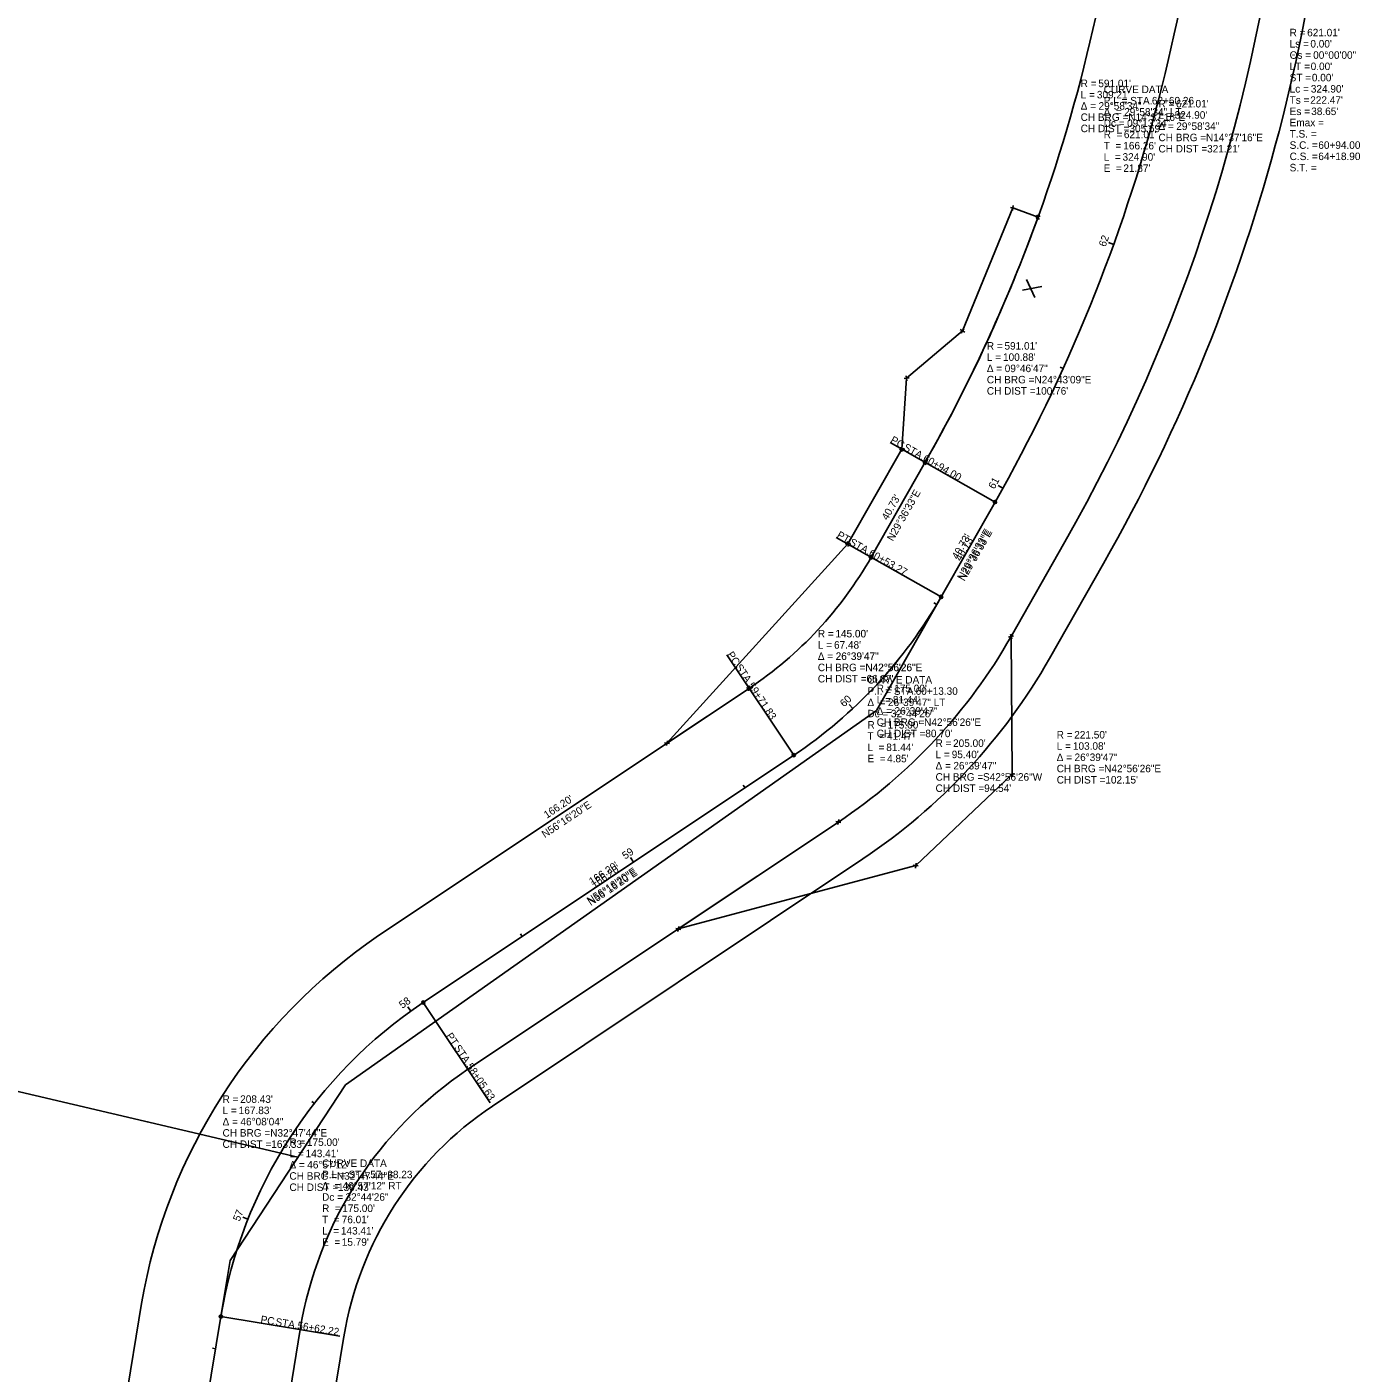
# Model space of a CAD drawing. Extents: x 2346746 to 2349554, y 247132 to 249252.
# Drawn here: x 2347228 to 2347725, y 247688 to 248191 of the extents above; entities that cross this region are included whole.
import ezdxf

# ---------------------------------------------------------------- set-up
doc = ezdxf.new("R2010")
doc.units = 0
for name, color, linetype in [('_CIVIL_CONSTRUCTION', 7, 'Continuous'), ('Default', 7, 'Continuous'), ('PF_X_Ground_Line', 7, 'Continuous'), ('UT_X_FO', 7, 'Continuous'), ('UT_X_Telecom', 7, 'Continuous'), ('V-SURV-ANNO', 7, 'Continuous'), ('V-SURV-IPF', 7, 'Continuous'), ('V-TOPO-ANNO', 7, 'Continuous'), ('V-TOPO-BNDY', 7, 'Continuous'), ('V-TOPO-FEAT', 7, 'Continuous'), ('V-TOPO-USER', 7, 'Continuous'), ('V-TOPO-WSHD', 7, 'Continuous'), ('V-UTIL-NGAS-STRC', 7, 'Continuous'), ('V-UTIL-STRM-STRC', 7, 'Continuous'), ('V-UTIL-WATR-LINE-ANNO', 7, 'Continuous'), ('V-UTIL-WATR-STRC', 7, 'Continuous')]:
    doc.layers.add(name, color=color, linetype=linetype)

msp = doc.modelspace()

# ---------------------------------------------------------------- linework, layer by layer
at = {"layer": '_CIVIL_CONSTRUCTION'}
for p, q in [((2347589.25, 248013.29), (2347550.12, 248035.52)), ((2347569.12, 247977.88), (2347530, 248000.11)), ((2347514.14, 247918.8), (2347489.16, 247956.22)), ((2347375.92, 247826.51), (2347400.9, 247789.09)), ((2347300.4, 247709.31), (2347344.8, 247702.02))]:
    msp.add_line(p, q, dxfattribs=at)
for centre in [(2347589.25, 248013.29), (2347569.12, 247977.88), (2347514.14, 247918.8), (2347375.92, 247826.51), (2347300.4, 247709.31)]:
    msp.add_circle(centre, 0.6, dxfattribs=at)
at = {"layer": 'Default'}
for p, q in [((2347548.13, 247948.47), (2347553.24, 247954.53)), ((2347548.13, 247948.47), (2347552.7, 247953.87)), ((2347525.99, 247947.23), (2347525.99, 247947.23))]:
    msp.add_line(p, q, dxfattribs=at)
at = {"layer": 'UT_X_FO'}
for p, q in [((2347569.12, 247977.88), (2347589.25, 248013.29)), ((2347375.92, 247826.51), (2347514.14, 247918.8)), ((2347286.36, 247623.78), (2347300.4, 247709.31))]:
    msp.add_line(p, q, dxfattribs=at)
for centre, radius, start, end in [((2347049.33, 248320.12), 621.01, 330.3908, 0.36691), ((2347416.98, 248064.34), 175, 303.7279, 330.3908), ((2347473.09, 247680.97), 175, 123.7279, 170.6811)]:
    msp.add_arc(centre, radius, start, end, dxfattribs=at)
at = {"layer": 'V-SURV-ANNO'}
for p, q in [((2347648.57, 248157.12), (2347647.41, 248157.44)), ((2347633.52, 248109.46), (2347631.64, 248110.14)), ((2347614.69, 248063.16), (2347613.59, 248063.65)), ((2347592.19, 248018.52), (2347590.44, 248019.49)), ((2347567.48, 247975.05), (2347566.45, 247975.66)), ((2347536.21, 247936.25), (2347534.85, 247937.71)), ((2347495.99, 247906.67), (2347495.32, 247907.67)), ((2347454.4, 247878.91), (2347453.29, 247880.57)), ((2347412.82, 247851.15), (2347412.15, 247852.15)), ((2347371.29, 247823.31), (2347370.12, 247824.94)), ((2347335.29, 247788.85), (2347334.35, 247789.59)), ((2347310.47, 247745.64), (2347308.62, 247746.38)), ((2347298.42, 247697.25), (2347297.23, 247697.44))]:
    msp.add_line(p, q, dxfattribs=at)
at = {"layer": 'V-TOPO-ANNO'}
for p, q in [((2347545, 247935.42), (2347569.12, 247977.88)), ((2347545, 247935.42), (2347569.12, 247977.88)), ((2347346.85, 247795.81), (2347545, 247935.42)), ((2347346.85, 247795.81), (2347545, 247935.42)), ((2347329.07, 247768.72), (2346848.6, 247881.75)), ((2347329.07, 247768.72), (2346848.6, 247881.75)), ((2347303.83, 247730.26), (2347346.85, 247795.81)), ((2347303.83, 247730.26), (2347346.85, 247795.81)), ((2347300.4, 247709.31), (2347303.83, 247730.26)), ((2347300.4, 247709.31), (2347303.83, 247730.26))]:
    msp.add_line(p, q, dxfattribs=at)
at = {"layer": 'V-TOPO-BNDY'}
for p, q in [((2347543.04, 247992.7), (2347563.17, 248028.11)), ((2347595.21, 247963.05), (2347615.33, 247998.46)), ((2347595.21, 247963.05), (2347615.33, 247998.46)), ((2347359.26, 247851.46), (2347497.49, 247943.75)), ((2347392.58, 247801.56), (2347530.8, 247893.85)), ((2347392.58, 247801.56), (2347530.8, 247893.85)), ((2347256.25, 247625.54), (2347270.79, 247714.16)), ((2347316.48, 247622.03), (2347330, 247704.45)), ((2347316.48, 247622.03), (2347330, 247704.45))]:
    msp.add_line(p, q, dxfattribs=at)
for centre, radius, start, end in [((2347049.33, 248320.12), 591.01, 330.3908, 0.36691), ((2347049.33, 248320.12), 651.01, 330.3908, 354.01806), ((2347049.33, 248320.12), 651.01, 330.3908, 354.01806), ((2347416.98, 248064.34), 145, 303.7279, 330.3908), ((2347416.98, 248064.34), 205, 303.7279, 330.3908), ((2347416.98, 248064.34), 205, 303.7279, 330.3908), ((2347476.23, 247678.94), 208.43, 124.1372, 170.2718), ((2347472.74, 247681.19), 144.62, 123.6631, 170.7459), ((2347472.74, 247681.19), 144.62, 123.6631, 170.7459)]:
    msp.add_arc(centre, radius, start, end, dxfattribs=at)
at = {"layer": 'V-TOPO-FEAT'}
for p, q in [((2347609.55, 247954.9), (2347629.68, 247990.31)), ((2347609.55, 247954.9), (2347629.68, 247990.31)), ((2347401.74, 247787.84), (2347539.96, 247880.12)), ((2347401.74, 247787.84), (2347539.96, 247880.12)), ((2347333.04, 247621.07), (2347346.28, 247701.78)), ((2347333.04, 247621.07), (2347346.28, 247701.78))]:
    msp.add_line(p, q, dxfattribs=at)
for centre, radius, start, end in [((2347049.33, 248320.12), 667.51, 330.3908, 0.36691), ((2347049.33, 248320.12), 667.51, 330.3908, 0.36691), ((2347416.98, 248064.34), 221.5, 303.7279, 330.3908), ((2347416.98, 248064.34), 221.5, 303.7279, 330.3908), ((2347473.09, 247680.97), 128.5, 123.7279, 170.6811), ((2347473.09, 247680.97), 128.5, 123.7279, 170.6811)]:
    msp.add_arc(centre, radius, start, end, dxfattribs=at)
at = {"layer": 'V-TOPO-USER'}
for p, q in [((2347594.96, 248123.18), (2347596.82, 248122.87)), ((2347595.74, 248122.1), (2347596.05, 248123.96)), ((2347604.46, 248119.21), (2347606.14, 248120.06)), ((2347605.73, 248118.79), (2347604.87, 248120.48)), ((2347576.28, 248077.62), (2347577.92, 248076.69)), ((2347576.64, 248076.33), (2347577.57, 248077.97)), ((2347556.15, 248060.41), (2347556.37, 248058.54)), ((2347555.32, 248059.37), (2347557.2, 248059.58)), ((2347553.57, 248032.78), (2347555.38, 248033.32)), ((2347554.74, 248032.15), (2347554.2, 248033.95)), ((2347562.26, 248027.84), (2347564.07, 248028.38)), ((2347563.44, 248027.21), (2347562.89, 248029.01)), ((2347533.44, 247997.39), (2347535.26, 247997.89)), ((2347534.6, 247996.73), (2347534.1, 247998.55)), ((2347542.13, 247992.44), (2347543.95, 247992.95)), ((2347543.3, 247991.79), (2347542.79, 247993.61)), ((2347594.3, 247962.8), (2347596.12, 247963.3)), ((2347595.46, 247962.14), (2347594.96, 247963.96)), ((2347496.56, 247943.92), (2347498.42, 247943.58)), ((2347497.32, 247942.82), (2347497.66, 247944.67)), ((2347465.93, 247923.47), (2347467.78, 247923.12)), ((2347466.68, 247922.37), (2347467.03, 247924.22)), ((2347594.73, 247911.64), (2347596.61, 247911.79)), ((2347595.74, 247910.77), (2347595.59, 247912.65)), ((2347530.61, 247892.92), (2347530.99, 247894.77)), ((2347529.88, 247894.03), (2347531.73, 247893.66)), ((2347558.72, 247877.75), (2347560.59, 247877.47)), ((2347559.52, 247876.68), (2347559.8, 247878.55)), ((2347470.87, 247853.04), (2347471.25, 247854.88)), ((2347470.14, 247854.15), (2347471.98, 247853.77))]:
    msp.add_line(p, q, dxfattribs=at)
at = {"layer": 'V-TOPO-WSHD'}
for p, q in [((2347577.1, 248077.15), (2347595.89, 248123.03)), ((2347595.89, 248123.03), (2347605.3, 248119.63)), ((2347556.26, 248059.47), (2347577.1, 248077.15)), ((2347554.47, 248033.05), (2347556.26, 248059.47)), ((2347534.35, 247997.64), (2347554.47, 248033.05)), ((2347466.85, 247923.29), (2347534.35, 247997.64)), ((2347595.67, 247911.71), (2347595.21, 247963.05)), ((2347559.66, 247877.61), (2347595.67, 247911.71)), ((2347471.06, 247853.96), (2347559.66, 247877.61))]:
    msp.add_line(p, q, dxfattribs=at)
at = {"layer": 'V-UTIL-NGAS-STRC'}
for p, q in [((2347577.1, 248077.15), (2347595.89, 248123.03)), ((2347595.89, 248123.03), (2347605.3, 248119.63)), ((2347556.26, 248059.47), (2347577.1, 248077.15)), ((2347554.47, 248033.05), (2347556.26, 248059.47)), ((2347534.35, 247997.64), (2347554.47, 248033.05)), ((2347563.17, 248028.11), (2347543.04, 247992.7)), ((2347466.85, 247923.29), (2347534.35, 247997.64)), ((2347595.21, 247963.05), (2347595.67, 247911.71)), ((2347497.49, 247943.75), (2347466.85, 247923.29)), ((2347595.67, 247911.71), (2347559.66, 247877.61)), ((2347471.06, 247853.96), (2347530.8, 247893.85)), ((2347559.66, 247877.61), (2347471.06, 247853.96))]:
    msp.add_line(p, q, dxfattribs=at)
for centre, radius, start, end in [((2347049.33, 248320.12), 591.01, 330.3908, 340.17061), ((2347416.98, 248064.34), 145, 303.7279, 330.3908), ((2347416.98, 248064.34), 205, 303.7279, 330.3908)]:
    msp.add_arc(centre, radius, start, end, dxfattribs=at)
at = {"layer": 'V-UTIL-STRM-STRC'}
for p, q in [((2347601.01, 248096.38), (2347604.08, 248089.65)), ((2347599.45, 248092.33), (2347606.66, 248093.78))]:
    msp.add_line(p, q, dxfattribs=at)

# ---------------------------------------------------------------- texts
at = {"layer": '_CIVIL_CONSTRUCTION'}
for s, rotation, p in [('PC', 330.3908, (2347549.95, 248035.66)), (' STA. ', 330.3908, (2347553.95, 248033.39)), ('60+94.00', 330.3908, (2347562.06, 248028.78)), ('PT', 330.3908, (2347529.96, 248000.18)), (' STA. ', 330.3908, (2347533.74, 247998.03)), ('60+53.27', 330.3908, (2347541.85, 247993.42)), ('PC', 303.7279, (2347489.11, 247956.37)), (' STA. ', 303.7279, (2347491.66, 247952.54)), ('59+71.83', 303.7279, (2347496.84, 247944.79)), ('PT', 303.7279, (2347384.26, 247814.08)), (' STA. ', 303.7279, (2347386.68, 247810.46)), ('58+05.63', 303.7279, (2347391.86, 247802.71)), ('PC', 350.6811, (2347315.04, 247706.94)), (' STA. ', 350.6811, (2347319.58, 247706.19)), ('56+62.22', 350.6811, (2347328.78, 247704.68))]:
    msp.add_text(s, height=2.8, rotation=rotation, dxfattribs=at).set_placement(p)
at = {"layer": 'Default'}
for s, p in [('R = ', (2347621.2, 248168.13)), ("591.01'", (2347627.79, 248168.13)), ('L = ', (2347621.2, 248163.93)), ("309.21'", (2347627.25, 248163.93)), ('Δ = ', (2347621.2, 248159.73)), ('29°58\'34"', (2347627.88, 248159.73)), ('CH BRG = ', (2347621.2, 248155.53)), ('N14°37\'16"E', (2347638.98, 248155.53)), ('CH DIST = ', (2347621.2, 248151.33)), ("305.69'", (2347639.39, 248151.33)), ('R = ', (2347586.19, 248070.17)), ("591.01'", (2347592.77, 248070.17)), ('L = ', (2347586.19, 248065.97)), ("100.88'", (2347592.23, 248065.97)), ('Δ = ', (2347586.19, 248061.77)), ('CH BRG = ', (2347586.19, 248057.57)), ('09°46\'47"', (2347592.87, 248061.77)), ('N24°43\'09"E', (2347603.97, 248057.57)), ('CH DIST = ', (2347586.19, 248053.37)), ("100.76'", (2347604.37, 248053.37)), ('R = ', (2347523.13, 247962.76)), ("145.00'", (2347529.71, 247962.76)), ('L = ', (2347523.13, 247958.56)), ("67.48'", (2347529.17, 247958.56)), ('Δ = ', (2347523.13, 247954.36)), ('26°39\'47"', (2347529.81, 247954.36)), ('CH BRG = ', (2347523.13, 247950.16)), ('N42°56\'26"E', (2347540.91, 247950.16)), ('CH DIST = ', (2347523.13, 247945.96)), ("66.87'", (2347541.31, 247945.96)), ('R = ', (2347301.02, 247789.04)), ("208.43'", (2347307.6, 247789.04)), ('L = ', (2347301.02, 247784.84)), ("167.83'", (2347307.06, 247784.84)), ('Δ = ', (2347301.02, 247780.64)), ('CH BRG = ', (2347301.02, 247776.44)), ('46°08\'04"', (2347307.7, 247780.64)), ('N32°47\'44"E', (2347318.8, 247776.44)), ('CH DIST = ', (2347301.02, 247772.24)), ("163.33'", (2347319.2, 247772.24))]:
    msp.add_text(s, height=2.8, dxfattribs=at).set_placement(p)
at = {"layer": 'PF_X_Ground_Line'}
for s, rotation, p in [('N29°36\'33"E', 60.3908, (2347577.87, 247983.54)), ('N56°16\'20"E', 33.7279, (2347438.45, 247862.49))]:
    msp.add_text(s, height=2.8, rotation=rotation, dxfattribs=at).set_placement(p)
at = {"layer": 'UT_X_Telecom'}
for s, p in [('R = ', (2347699.17, 248187.11)), ("621.01'", (2347705.71, 248187.11)), ('Θs = ', (2347699.17, 248178.71)), ('Ls = ', (2347699.17, 248182.91)), ("0.00'", (2347706.91, 248182.91)), ('00°00\'00"', (2347707.95, 248178.71)), ('LT = ', (2347699.17, 248174.51)), ("0.00'", (2347707.02, 248174.51)), ('ST = ', (2347699.17, 248170.31)), ("0.00'", (2347707.47, 248170.31)), ('CURVE DATA', (2347629.79, 248165.89)), ('Lc = ', (2347699.17, 248166.11)), ("324.90'", (2347707.08, 248166.11)), ('P.I. = STA. ', (2347629.79, 248161.69)), ('62+60.26', (2347647.78, 248161.69)), ('Ts = ', (2347699.17, 248161.91)), ("222.47'", (2347706.85, 248161.91)), ('Δ  = ', (2347629.79, 248157.49)), ('Dc = ', (2347629.79, 248153.29)), ('29°58\'34" LT', (2347637.43, 248157.49)), ('09°13\'34"', (2347638.53, 248153.29)), ('Es = ', (2347699.17, 248157.71)), ('Emax = ', (2347699.17, 248153.51)), ("38.65'", (2347707.22, 248157.71)), ('R  = ', (2347629.79, 248149.09)), ("621.01'", (2347637.32, 248149.09)), ('T.S. = ', (2347699.17, 248149.31)), ('T  = ', (2347629.79, 248144.89)), ("166.26'", (2347637.11, 248144.89)), ('S.C. = ', (2347699.17, 248145.11)), ('60+94.00', (2347709.87, 248145.11)), ('L  = ', (2347629.79, 248140.69)), ("324.90'", (2347636.82, 248140.69)), ('C.S. = ', (2347699.17, 248140.91)), ('64+18.90', (2347709.87, 248140.91)), ('E  = ', (2347629.79, 248136.49)), ("21.87'", (2347637.13, 248136.49)), ('S.T. = ', (2347699.17, 248136.71)), ('CURVE DATA', (2347541.63, 247945.54)), ('Δ  = ', (2347541.63, 247937.14)), ('P.I. = STA. ', (2347541.63, 247941.34)), ('26°39\'47" LT', (2347549.28, 247937.14)), ('60+13.30', (2347559.63, 247941.34)), ('Dc = ', (2347541.63, 247932.94)), ('32°44\'26"', (2347550.38, 247932.94)), ('R  = ', (2347541.63, 247928.74)), ("175.00'", (2347549.17, 247928.74)), ('T  = ', (2347541.63, 247924.54)), ("41.47'", (2347548.95, 247924.54)), ('L  = ', (2347541.63, 247920.34)), ("81.44'", (2347548.67, 247920.34)), ('E  = ', (2347541.63, 247916.14)), ("4.85'", (2347548.98, 247916.14)), ('CURVE DATA', (2347338.16, 247765.11)), ('Δ  = ', (2347338.16, 247756.71)), ('P.I. = STA. ', (2347338.16, 247760.91)), ('46°57\'12" RT', (2347345.8, 247756.71)), ('57+38.23', (2347356.15, 247760.91)), ('Dc = ', (2347338.16, 247752.51)), ('32°44\'26"', (2347346.9, 247752.51)), ('R  = ', (2347338.16, 247748.31)), ("175.00'", (2347345.69, 247748.31)), ('T  = ', (2347338.16, 247744.11)), ("76.01'", (2347345.48, 247744.11)), ('L  = ', (2347338.16, 247739.91)), ("143.41'", (2347345.19, 247739.91)), ('E  = ', (2347338.16, 247735.71)), ("15.79'", (2347345.5, 247735.71))]:
    msp.add_text(s, height=2.8, dxfattribs=at).set_placement(p)
at = {"layer": 'V-SURV-ANNO'}
for s, rotation, p in [('62', 70.1706, (2347630.46, 248108.34)), ('61', 60.9444, (2347588.98, 248017.89)), ('60', 42.9499, (2347532.94, 247936.61)), ('59', 33.7279, (2347451.26, 247879.82)), ('58', 35.5715, (2347368.1, 247824.1)), ('57', 68.312, (2347307.37, 247744.59))]:
    msp.add_text(s, height=2.8, rotation=rotation, dxfattribs=at).set_placement(p)
at = {"layer": 'V-SURV-IPF'}
for s, rotation, p in [("40.73'", 60.3908, (2347576.53, 247990.97)), ("166.20'", 33.7279, (2347439.66, 247869.11))]:
    msp.add_text(s, height=2.8, rotation=rotation, dxfattribs=at).set_placement(p)
at = {"layer": 'V-UTIL-WATR-LINE-ANNO'}
for s, p in [('R = ', (2347650.23, 248160.56)), ("621.01'", (2347656.77, 248160.56)), ('L = ', (2347650.23, 248156.36)), ("324.90'", (2347656.27, 248156.36)), ('Δ = ', (2347650.23, 248152.16)), ('CH BRG = ', (2347650.23, 248147.96)), ('29°58\'34"', (2347656.88, 248152.16)), ('N14°37\'16"E', (2347667.95, 248147.96)), ('CH DIST = ', (2347650.23, 248143.76)), ("321.21'", (2347668.37, 248143.76)), ('R = ', (2347523.13, 247962.76)), ("145.00'", (2347529.66, 247962.76)), ('L = ', (2347523.13, 247958.56)), ("67.48'", (2347529.16, 247958.56)), ('Δ = ', (2347523.13, 247954.36)), ('26°39\'47"', (2347529.77, 247954.36)), ('CH BRG = ', (2347523.13, 247950.16)), ('N42°56\'26"E', (2347540.84, 247950.16)), ('CH DIST = ', (2347523.13, 247945.96)), ("66.87'", (2347541.27, 247945.96)), ('R = ', (2347545.09, 247942.32)), ("175.00'", (2347551.63, 247942.32)), ('L = ', (2347545.09, 247938.12)), ("81.44'", (2347551.13, 247938.12)), ('Δ = ', (2347545.09, 247933.92)), ('26°39\'47"', (2347551.74, 247933.92)), ('CH BRG = ', (2347545.09, 247929.72)), ('N42°56\'26"E', (2347562.8, 247929.72)), ('CH DIST = ', (2347545.09, 247925.52)), ("80.70'", (2347563.23, 247925.52)), ('R = ', (2347567.05, 247921.89)), ("205.00'", (2347573.59, 247921.89)), ('R = ', (2347612.26, 247925.03)), ("221.50'", (2347618.8, 247925.03)), ('L = ', (2347567.05, 247917.69)), ("95.40'", (2347573.09, 247917.69)), ('L = ', (2347612.26, 247920.83)), ("103.08'", (2347618.3, 247920.83)), ('Δ = ', (2347567.05, 247913.49)), ('26°39\'47"', (2347573.7, 247913.49)), ('Δ = ', (2347612.26, 247916.63)), ('CH BRG = ', (2347612.26, 247912.43)), ('26°39\'47"', (2347618.91, 247916.63)), ('N42°56\'26"E', (2347629.97, 247912.43)), ('CH BRG = ', (2347567.05, 247909.29)), ('S42°56\'26"W', (2347584.76, 247909.29)), ('CH DIST = ', (2347612.26, 247908.23)), ("102.15'", (2347630.4, 247908.23)), ('CH DIST = ', (2347567.05, 247905.09)), ("94.54'", (2347585.19, 247905.09)), ('R = ', (2347325.98, 247772.96)), ("175.00'", (2347332.52, 247772.96)), ('L = ', (2347325.98, 247768.76)), ("143.41'", (2347332.02, 247768.76)), ('Δ = ', (2347325.98, 247764.56)), ('46°57\'12"', (2347332.63, 247764.56)), ('CH BRG = ', (2347325.98, 247760.36)), ('CH DIST = ', (2347325.98, 247756.16)), ('N32°47\'44"E', (2347343.69, 247760.36)), ("139.43'", (2347344.12, 247756.16))]:
    msp.add_text(s, height=2.8, dxfattribs=at).set_placement(p)
for s, rotation, p in [("40.73'", 60.3908, (2347575.34, 247991.65)), ('N29°36\'33"E', 60.3908, (2347577.34, 247983.84)), ('N56°16\'20"E', 33.7279, (2347438.12, 247862.99)), ("166.20'", 33.7279, (2347438.9, 247870.24))]:
    msp.add_text(s, height=2.8, rotation=rotation, dxfattribs=at).set_placement(p)
at = {"layer": 'V-UTIL-WATR-STRC'}
for s, rotation, p in [("40.73'", 60.3908, (2347549.14, 248006.26)), ('N29°36\'33"E', 60.3908, (2347551.14, 247998.45)), ('N56°16\'20"E', 33.7279, (2347421.26, 247887.8)), ("166.20'", 33.7279, (2347422.04, 247895.06))]:
    msp.add_text(s, height=2.8, rotation=rotation, dxfattribs=at).set_placement(p)

doc.saveas('drawing.dxf')
